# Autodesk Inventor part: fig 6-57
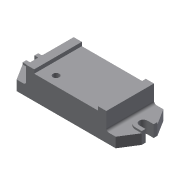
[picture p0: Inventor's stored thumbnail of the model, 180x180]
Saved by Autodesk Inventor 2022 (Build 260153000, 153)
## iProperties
Created: 2001-12
Part Number: fig 6-57
Document SubType Name: Modeling
Designer: Renu Muthoo
Density: 1 g/cm^3
Material: Generic
Appearance: Default
Control State: 0
Master: False
Checked Out: False
Shininess: 77.0
Angle Display Precision: 2
Document Length Units: 11269
Document Angle Units: 11279
Document Time Units: 11290
Document Mass Units: 11283
Document Length Units Precision: 3
Document Angle Units Precision: 2
Density: 0.0
Volumn: 0.0
Area: 0.0
PropertySet Name: Model Information
Author: Renu Muthoo
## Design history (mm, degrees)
sketch "Sketch3"
  geometry: L1 (-59.119, -24.322)-(-59.119, 19.678); L2 (-59.119, 19.678)-(-46.119, 19.678); L3 (-46.119, 19.678)-(-46.119, 13.678); L4 (-46.119, 13.678)-(55.881, 13.678); L5 (55.881, 13.678)-(55.881, 19.678); L6 (55.881, 19.678)-(68.881, 19.678); L7 (68.881, 19.678)-(68.881, -24.322); L8 (68.881, -24.322)-(-59.119, -24.322)
  constraints: 16 end point, 2 equal length
  dimensions: "d10" = 13 distance of L1.end L2.end; "d11" = 102 distance of L3.end L4.end; "d13" = 44 distance between parallel lines of L2 L8; "d14" = 6 distance of L2.end L3.end
extrude "Extrusion1" new body sketch "Sketch3" distance "d15" = 76; taper "d16" = 0 deg
sketch "Sketch4"
  geometry: L1 (0, 0)-(0, 76) reference; L2 (0, 76)-(-15, 76); L3 (-15, 76)-(-31, 50.5); L4 (-31, 50.5)-(-31, 44.5); L5 (-31, 44.5)-(-21, 44.5); L6 (-21, 31.5)-(-31, 31.5); L7 (-31, 31.5)-(-31, 25.5); L8 (-31, 25.5)-(-15, 0); L9 (-15, 0)-(0, 0); L10 (128, 76)-(0, 76) reference; L11 (0, 0)-(128, 0) reference; A1 r 6.5 centre (-21, 38) between (-21, 31.5) and (-21, 44.5)
  constraints: 16 end point, 4 equal length, 3 collinear, 3 parallel, 2 perpendicular, 2 point on circle, 2 tangent, 1 centre point
  dimensions: "d17" = 13 distance between parallel lines of L6 L5; "d18" = 25 distance of L3.end L7.end; "d19" = 10 distance of L6.start L6.end; "d20" = 15 distance of L8.end L1.start; "d21" = 16 horizontal distance of L7.end L8.end
extrude "Extrusion2" join sketch "Sketch4" distance "d22" = 16; taper "d23" = 0 deg
sketch "Sketch5"
  geometry: L1 (-159, 44.5)-(-159, 50.5) reference; L2 (-149, 44.5)-(-159, 44.5) reference; L3 (-159, 31.5)-(-149, 31.5) reference; L4 (-159, 25.5)-(-159, 31.5) reference; L5 (-159, 25.5)-(-149, 25.5); L6 (-149, 50.5)-(-159, 50.5); A1 r 6.5 centre (-149, 38) between (-149, 31.5) and (-149, 44.5) reference; A2 r 12.5 centre (-149, 38) between (-149, 25.5) and (-149, 50.5)
  constraints: 4 end point, 2 point on circle, 2 tangent, 1 centre point, 1 parallel, 1 perpendicular
extrude "Extrusion3" join sketch "Sketch5" distance "d24" = 19; taper "d25" = 0 deg
workplane "Work Plane1"
mirror "Mirror1"
fillet "Fillet1" dims "d27" = 4
sketch "Sketch6"
  geometry: L1 (0, 0)-(0, 76) reference; L2 (0, 0)-(102, 0) reference; 1 further point
  dimensions: "d28" = 20 distance from line of L1 point (20, 15); "d29" = 15 distance from line of L2 point (20, 15)
hole "Hole1" sketch "Sketch6" at (20, 15) diameter "d30" = 10; stored, may be unused: countersink angle "d34" = 82 deg, drill point angle "d36" = 118 deg; dims "d31" = 6, "d32" = 4, "d33" = 2, "d35" = 15
sketch "Sketch7"
  geometry: C1 r 5 at (20, 15) reference; 3 further points
  constraints: 4 other
body "Solid1"
other parameters: "d26" = -64
